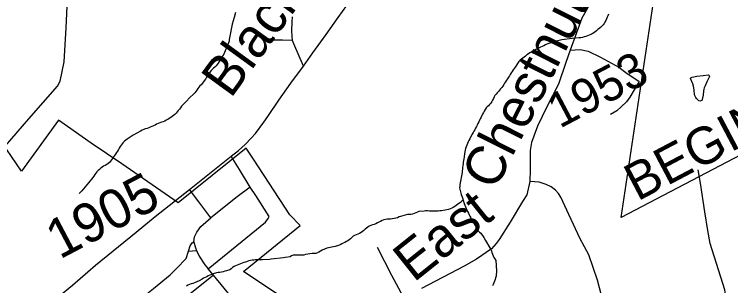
# Model space of a CAD drawing. Extents: x 1379448 to 1382868, y 593769 to 596827.
# Drawn here: x 1379666.4 to 1379935.9, y 595497.8 to 595600.1 of the extents above; entities that cross this region are included whole.
import ezdxf

# ---------------------------------------------------------------- set-up
doc = ezdxf.new("R2010")
doc.units = 0
for name, color, linetype in [('Old_Level_11', 7, 'Continuous'), ('Old_Level_32', 7, 'Continuous'), ('Old_Level_35', 7, 'Continuous'), ('Old_Level_48', 7, 'Continuous'), ('Old_Level_49', 7, 'Continuous'), ('Old_Level_62', 7, 'Continuous'), ('Old_Level_8', 7, 'Continuous')]:
    doc.layers.add(name, color=color, linetype=linetype)

msp = doc.modelspace()

# ---------------------------------------------------------------- linework, layer by layer
at = {"layer": 'Old_Level_11'}
for p, q in [((1379894.75, 595523.47), (1379909.86, 595624.29)), ((1380038.89, 595599.46), (1379894.75, 595523.47))]:
    msp.add_line(p, q, dxfattribs=at)
at = {"layer": 'Old_Level_32'}
for points in [[(1379640.12, 595529.74), (1379643.82, 595532.3), (1379648.19, 595535.83), (1379652.41, 595539.5), (1379660.54, 595547.76), (1379671.85, 595560.64), (1379682.66, 595573), (1379683.63, 595574.88), (1379685.11, 595582.2), (1379685.85, 595595.01), (1379686.98, 595619.75), (1379687.08, 595622.03), (1379687.13, 595624.42), (1379687.25, 595625.44), (1379687.39, 595628.93), (1379687.49, 595632.65), (1379687.77, 595638.22), (1379687.48, 595646), (1379686.94, 595658.47)], [(1379899.06, 595630.19), (1379889.58, 595617.21), (1379886.27, 595610.7), (1379883.76, 595605.7), (1379879.92, 595598.7), (1379877.96, 595593.17), (1379875.58, 595586.55)], [(1379683.35, 595493.98), (1379688.24, 595498.01), (1379696.92, 595505.49), (1379712.22, 595517.91), (1379719.4, 595523.93), (1379732.24, 595534.03), (1379737.9, 595538.56), (1379748.01, 595546.67), (1379750.73, 595548.72), (1379753.22, 595551.06), (1379755.55, 595553.38), (1379757.18, 595555.22), (1379760.31, 595559.39), (1379761.72, 595561.6), (1379765.93, 595567.69), (1379770.47, 595574.1), (1379775.16, 595580.59), (1379778.74, 595585.58), (1379783.72, 595592.51), (1379788.24, 595598.85), (1379791.48, 595603.37)], [(1379875.58, 595586.55), (1379879.35, 595586.8), (1379882.36, 595586.26), (1379886.91, 595583.9), (1379893.81, 595580.13), (1379896.43, 595578.18), (1379901.51, 595574.72)], [(1379875.58, 595586.55), (1379873.89, 595581.91), (1379871.1, 595573.72), (1379866.78, 595565.26), (1379863.25, 595557.99), (1379860.94, 595551.72), (1379860.52, 595548.81), (1379860.43, 595545.83), (1379860.45, 595541.65), (1379860.35, 595537.12)], [(1379923.57, 595461.53), (1379926.3, 595467.79), (1379932.44, 595483.19), (1379933.97, 595487.9), (1379934.26, 595489.83), (1379934.28, 595492.82), (1379933.76, 595496.17), (1379928.2, 595513.67), (1379927.29, 595518.6), (1379926.27, 595525.62), (1379924.52, 595536.46), (1379923.75, 595541.51)], [(1379860.35, 595537.12), (1379859.21, 595532.1), (1379857.66, 595529.56), (1379852.97, 595521.73), (1379848.78, 595515.26), (1379847.74, 595513.74), (1379845.88, 595511.74), (1379840.23, 595507.84), (1379835.65, 595505.19), (1379819.59, 595496.7)], [(1379923.57, 595461.53), (1379917.03, 595465.49), (1379898.01, 595477), (1379894.52, 595479.95), (1379892.42, 595482.24), (1379890.47, 595485.05), (1379888.73, 595488.79), (1379885.86, 595499.84), (1379882.5, 595509.41), (1379879.34, 595515.46), (1379874.98, 595524.63), (1379872.01, 595531.16), (1379871.14, 595532.59), (1379869.97, 595533.81), (1379868.42, 595535.06), (1379866.55, 595535.92), (1379863.91, 595536.76), (1379860.35, 595537.12)], [(1379812.86, 595493.5), (1379808.42, 595501.66), (1379803.01, 595512.18)]]:
    msp.add_lwpolyline(points, dxfattribs=at)
at = {"layer": 'Old_Level_35'}
for p, q in [((1379731.9, 595510.79), (1379734.96, 595511.01)), ((1379741.35, 595501.72), (1379739.38, 595504.2))]:
    msp.add_line(p, q, dxfattribs=at)
for points in [[(1379771, 595590.16), (1379770.78, 595593.72), (1379770.98, 595597.38), (1379771, 595599.12)], [(1379771, 595590.16), (1379767.23, 595590.35), (1379763.32, 595590.36)], [(1379775.16, 595580.59), (1379771.52, 595588.94), (1379771, 595590.16)], [(1379901.51, 595574.72), (1379899.63, 595571.66), (1379897.94, 595568.82), (1379896.74, 595567.04), (1379894.76, 595565.19), (1379893.06, 595563.72), (1379890.75, 595562.27)], [(1379755.1, 595534.98), (1379751.17, 595541.63), (1379748.01, 595546.67)], [(1379740.35, 595523.42), (1379735.79, 595529.45), (1379732.24, 595534.03)], [(1379739.38, 595504.2), (1379760.86, 595521.73), (1379761.93, 595523.12), (1379762.29, 595523.86), (1379757.26, 595531.79), (1379755.1, 595534.98)], [(1379755.1, 595534.98), (1379750.23, 595531.3), (1379740.35, 595523.42)], [(1379733.98, 595514.3), (1379734.23, 595516.18), (1379735.06, 595518.03), (1379736.58, 595520.1), (1379740.35, 595523.42)], [(1379731.9, 595510.79), (1379732.57, 595512.85), (1379733.36, 595513.97), (1379733.98, 595514.3)], [(1379733.98, 595514.3), (1379734.49, 595512.03), (1379734.96, 595511.01)], [(1379705.01, 595485.66), (1379718.78, 595496.77), (1379724.96, 595501.92), (1379727.36, 595504.29), (1379730.99, 595508), (1379731.9, 595510.79)], [(1379734.96, 595511.01), (1379735.89, 595508.97), (1379738.09, 595505.62), (1379739.38, 595504.2)], [(1379741.35, 595501.72), (1379734.34, 595496.06), (1379711.06, 595477.68)], [(1379753.75, 595487.17), (1379749.3, 595491.92), (1379741.35, 595501.72)]]:
    msp.add_lwpolyline(points, dxfattribs=at)
at = {"layer": 'Old_Level_48'}
msp.add_line((1379706.83, 595543.73), (1379695.33, 595551.52), dxfattribs=at)
for points in [[(1379695.33, 595551.52), (1379682.96, 595560.25), (1379669.13, 595540.96), (1379663.48, 595549.25)], [(1379937.54, 595313.11), (1379935.68, 595324.14), (1379926.32, 595374.29), (1379931.87, 595375.52), (1379929.49, 595387.82), (1379937.84, 595389.12), (1379931.29, 595425.64), (1379904.13, 595417.61), (1379896.01, 595407.11), (1379890.61, 595410.69), (1379752.56, 595503.09), (1379773.98, 595520.53), (1379770.04, 595524.52), (1379756.34, 595545.51), (1379753.67, 595549.68), (1379728.08, 595528.98), (1379706.83, 595543.73)]]:
    msp.add_lwpolyline(points, dxfattribs=at)
at = {"layer": 'Old_Level_49'}
msp.add_line((1379706.83, 595543.73), (1379695.33, 595551.52), dxfattribs=at)
for points in [[(1379695.33, 595551.52), (1379682.96, 595560.25), (1379669.13, 595540.96), (1379663.48, 595549.25)], [(1379937.54, 595313.11), (1379935.68, 595324.14), (1379926.32, 595374.29), (1379931.87, 595375.52), (1379929.49, 595387.82), (1379937.84, 595389.12), (1379931.29, 595425.64), (1379904.13, 595417.61), (1379896.01, 595407.11), (1379890.61, 595410.69), (1379752.56, 595503.09), (1379773.98, 595520.53), (1379770.04, 595524.52), (1379756.34, 595545.51), (1379753.67, 595549.68), (1379728.08, 595528.98), (1379706.83, 595543.73)]]:
    msp.add_lwpolyline(points, dxfattribs=at)
at = {"layer": 'Old_Level_62'}
for points in [[(1379749.55, 595600.74), (1379749.06, 595598.91), (1379748.39, 595596.37), (1379748.24, 595595.73), (1379748.1, 595595.09), (1379747.58, 595592.52), (1379747.27, 595590.61), (1379747.16, 595589.97), (1379746.97, 595589.35), (1379746.75, 595588.73), (1379746.51, 595588.12), (1379746.26, 595587.5), (1379746, 595586.9), (1379745.73, 595586.3), (1379745.45, 595585.71), (1379745.16, 595585.12), (1379744.86, 595584.53), (1379744.55, 595583.95), (1379744.22, 595583.38), (1379743.88, 595582.82), (1379743.52, 595582.27), (1379743.14, 595581.74), (1379742.73, 595581.22), (1379742.32, 595580.71), (1379741.88, 595580.22), (1379741.38, 595579.81), (1379740.89, 595579.37), (1379740.45, 595578.88), (1379740.04, 595578.37), (1379739.64, 595577.84), (1379739.28, 595577.3), (1379738.93, 595576.74), (1379738.6, 595576.17), (1379738.27, 595575.6), (1379736.7, 595573.57), (1379736.24, 595573.09), (1379735.8, 595572.61), (1379735.39, 595572.09), (1379735.04, 595571.53), (1379734.7, 595570.97), (1379734.32, 595570.45), (1379733.83, 595570.01), (1379732.37, 595568.68), (1379731.02, 595567.29), (1379730.13, 595566.36), (1379729.25, 595565.42), (1379728.85, 595564.9), (1379728.47, 595564.36), (1379728.09, 595563.82), (1379727.69, 595563.29), (1379727.28, 595562.79), (1379726.79, 595562.37), (1379725.76, 595561.57), (1379725.23, 595561.19), (1379724.69, 595560.8), (1379724.13, 595560.45), (1379723.57, 595560.13), (1379722.97, 595559.86), (1379722.36, 595559.62), (1379721.74, 595559.39), (1379721.12, 595559.16), (1379720.52, 595558.91), (1379719.92, 595558.64), (1379719.33, 595558.35), (1379718.74, 595558.07), (1379718.14, 595557.79), (1379717.55, 595557.52), (1379716.94, 595557.27), (1379716.31, 595557.08), (1379715.67, 595556.91), (1379715.06, 595556.69), (1379714.46, 595556.42), (1379713.88, 595556.1), (1379711.05, 595554.52), (1379708.87, 595553.09), (1379708.33, 595552.71), (1379707.82, 595552.29), (1379707.37, 595551.82), (1379706.98, 595551.29), (1379706.6, 595550.75), (1379706.24, 595550.21), (1379705.88, 595549.66), (1379705.52, 595549.1), (1379705.16, 595548.54), (1379704.81, 595547.98), (1379704.46, 595547.43), (1379704.1, 595546.87), (1379703.73, 595546.33), (1379703.36, 595545.79), (1379702.97, 595545.26), (1379702.58, 595544.74), (1379702.17, 595544.24), (1379701.7, 595543.8), (1379701.15, 595543.44)], [(1379889.94, 595600.19), (1379889.72, 595599.57), (1379889.47, 595598.96), (1379889.2, 595598.36), (1379888.92, 595597.76), (1379888.63, 595597.17), (1379888.3, 595596.6), (1379887.92, 595596.07), (1379887.49, 595595.59), (1379887, 595595.14), (1379886.5, 595594.72), (1379885.98, 595594.31), (1379885.45, 595593.91), (1379884.93, 595593.51), (1379884.39, 595593.13), (1379883.84, 595592.77), (1379883.26, 595592.47), (1379882.66, 595592.2), (1379882.05, 595591.97), (1379881.42, 595591.75), (1379880.79, 595591.55), (1379880.16, 595591.37), (1379879.52, 595591.22), (1379878.87, 595591.2), (1379877.57, 595591.08), (1379876.26, 595590.92), (1379872.4, 595590.42), (1379869.85, 595589.9), (1379866.8, 595588.78), (1379866.2, 595588.53)], [(1379866.2, 595588.53), (1379865.6, 595588.25), (1379865, 595587.97), (1379864.41, 595587.69), (1379863.83, 595587.4), (1379863.24, 595587.1), (1379862.65, 595586.8), (1379862.07, 595586.51), (1379861.49, 595586.2), (1379860.92, 595585.87), (1379860.36, 595585.52), (1379859.82, 595585.15), (1379859.29, 595584.76), (1379858.75, 595584.37), (1379858.23, 595583.97), (1379857.71, 595583.57), (1379857.19, 595583.16), (1379856.68, 595582.75), (1379856.18, 595582.35), (1379854.78, 595580.21), (1379854.42, 595579.66), (1379854.07, 595579.11), (1379853.71, 595578.56), (1379853.36, 595578), (1379853.01, 595577.45), (1379852.66, 595576.89), (1379852.3, 595576.34), (1379851.95, 595575.78), (1379851.6, 595575.23), (1379851.24, 595574.68), (1379850.88, 595574.13), (1379850.52, 595573.59), (1379850.15, 595573.04), (1379849.78, 595572.51), (1379849.38, 595571.98), (1379848.95, 595571.48), (1379848.51, 595571), (1379848.06, 595570.51), (1379847.63, 595570.02), (1379847.23, 595569.5), (1379846.91, 595568.93), (1379846.65, 595568.33), (1379846.37, 595567.73), (1379846.02, 595567.17), (1379845.63, 595566.65), (1379845.2, 595566.14), (1379844.77, 595565.64), (1379844.34, 595565.16), (1379843.88, 595564.78), (1379843.54, 595564.21), (1379843.22, 595563.64), (1379842.9, 595563.07), (1379842.59, 595562.48), (1379842.28, 595561.9), (1379841.99, 595561.32), (1379841.69, 595560.73), (1379841.4, 595560.14), (1379841.12, 595559.55), (1379840.84, 595558.95), (1379840.55, 595558.36), (1379840.26, 595557.77), (1379839.97, 595557.19), (1379839.66, 595556.6), (1379839.32, 595556.04), (1379838.98, 595555.48), (1379838.67, 595554.91), (1379838.05, 595553.74), (1379837.75, 595553.16), (1379837.45, 595552.57), (1379837.16, 595551.98), (1379836.88, 595551.39), (1379836.63, 595550.78), (1379836.4, 595550.17), (1379836.21, 595549.55), (1379836.05, 595548.91), (1379835.93, 595548.27), (1379835.81, 595547.62), (1379835.6, 595546.32), (1379835.49, 595545.67), (1379835.4, 595545.02), (1379835.3, 595544.37), (1379835.22, 595543.72), (1379835.13, 595543.07), (1379835.05, 595542.41), (1379834.97, 595541.77), (1379834.89, 595541.11), (1379834.86, 595540.46), (1379834.8, 595539.8), (1379834.69, 595539.16), (1379834.55, 595538.52), (1379834.41, 595537.88), (1379834.27, 595537.23), (1379834.16, 595536.58), (1379834.07, 595535.94), (1379833.99, 595535.28), (1379833.91, 595534.63), (1379834.58, 595532.11), (1379834.76, 595531.48), (1379834.97, 595530.86), (1379835.28, 595529.98)], [(1379921.41, 595576.38), (1379923.25, 595576.75), (1379925.53, 595577.09), (1379927.45, 595577.29), (1379927.72, 595577.2), (1379927.9, 595577.04), (1379927.98, 595576.8), (1379927.86, 595576.37), (1379927, 595574.62), (1379926.31, 595573.15), (1379925.95, 595572.37), (1379925.81, 595571.87), (1379925.73, 595571.22), (1379925.6, 595569.61), (1379925.25, 595567.94), (1379925.07, 595567.64), (1379924.72, 595567.45), (1379924.39, 595567.39), (1379924.01, 595567.54), (1379923.09, 595568.32), (1379922.8, 595568.7), (1379922.52, 595569.2), (1379922.34, 595569.79), (1379922.21, 595571.46), (1379922.13, 595572.32), (1379921.96, 595573.01), (1379921.64, 595573.85), (1379920.78, 595575.9), (1379920.76, 595576.07), (1379920.9, 595576.2), (1379921.15, 595576.3), (1379921.41, 595576.38)], [(1379701.15, 595543.44), (1379700.57, 595543.12), (1379699.99, 595542.8), (1379699.43, 595542.43), (1379698.9, 595542.04), (1379698.39, 595541.63), (1379697.9, 595541.18), (1379697.48, 595540.69), (1379697.06, 595540.18), (1379696.67, 595539.65), (1379696.28, 595539.13), (1379695.89, 595538.6), (1379694.28, 595536.52), (1379691.75, 595533.51), (1379690.82, 595532.57)], [(1379835.28, 595529.98), (1379834.75, 595529.6), (1379834.23, 595529.2), (1379833.7, 595528.81), (1379833.17, 595528.41), (1379832.64, 595528.03), (1379832.09, 595527.67), (1379831.54, 595527.33), (1379830.96, 595527.03), (1379830.35, 595526.77), (1379829.72, 595526.55), (1379829.1, 595526.36), (1379828.46, 595526.21), (1379827.81, 595526.1), (1379827.16, 595526.02), (1379826.5, 595525.96), (1379825.85, 595525.92), (1379825.19, 595525.89), (1379824.53, 595525.88), (1379823.88, 595525.87), (1379823.22, 595525.89), (1379822.57, 595525.92), (1379821.91, 595525.95), (1379821.26, 595525.96), (1379820.6, 595525.92), (1379818.65, 595525.8), (1379818.05, 595525.55), (1379817.45, 595525.27), (1379816.84, 595524.99), (1379816.24, 595524.77), (1379815.59, 595524.68), (1379814.93, 595524.67), (1379814.28, 595524.58), (1379811.75, 595523.89), (1379811.13, 595523.7), (1379810.55, 595523.38), (1379809.91, 595523.23), (1379809.26, 595523.1), (1379808.61, 595523), (1379807.96, 595522.92), (1379807.31, 595522.88), (1379806.65, 595522.83), (1379806, 595522.72), (1379805.36, 595522.56), (1379804.75, 595522.33), (1379804.16, 595522.05), (1379803.57, 595521.75), (1379803, 595521.44), (1379802.41, 595521.15), (1379801.8, 595520.89), (1379801.17, 595520.68), (1379800.55, 595520.47), (1379799.94, 595520.22), (1379799.39, 595519.9), (1379798.87, 595519.5), (1379798.37, 595519.06), (1379797.88, 595518.61), (1379797.37, 595518.19), (1379796.83, 595517.83), (1379796.25, 595517.53), (1379795.65, 595517.26), (1379795.04, 595516.99), (1379794.44, 595516.72), (1379793.87, 595516.41), (1379793.36, 595516), (1379792.92, 595515.5), (1379791.91, 595514.72), (1379791.33, 595514.41), (1379790.74, 595514.11), (1379790.15, 595513.82), (1379789.56, 595513.53), (1379788.97, 595513.25), (1379788.37, 595512.97), (1379787.16, 595512.53), (1379786.53, 595512.38), (1379785.88, 595512.29), (1379785.22, 595512.22), (1379784.58, 595512.11), (1379783.96, 595511.91), (1379782.16, 595511.16), (1379781.59, 595510.83), (1379781.02, 595510.47), (1379780.44, 595510.17), (1379779.82, 595509.99), (1379779.18, 595509.91), (1379778.51, 595509.87), (1379775.91, 595509.5), (1379775.27, 595509.36), (1379774.61, 595509.29), (1379773.96, 595509.28), (1379773.3, 595509.31), (1379772.64, 595509.34), (1379771.98, 595509.34), (1379771.34, 595509.28), (1379770.71, 595509.05), (1379770.18, 595508.72), (1379768.25, 595508.39), (1379767.61, 595508.29), (1379763.05, 595507.8), (1379762.4, 595507.72)], [(1379835.28, 595529.98), (1379835.7, 595528.74), (1379835.92, 595528.12), (1379836.17, 595527.51), (1379836.42, 595526.91), (1379836.69, 595526.31), (1379836.96, 595525.71), (1379837.25, 595525.12), (1379837.53, 595524.53), (1379837.82, 595523.94), (1379838.13, 595523.36), (1379838.43, 595522.78), (1379838.75, 595522.2), (1379839.08, 595521.64), (1379839.42, 595521.07), (1379840.31, 595519.62), (1379840.6, 595519.03), (1379840.98, 595518.5), (1379841.44, 595518.03), (1379841.89, 595517.55), (1379843.03, 595515.97), (1379843.74, 595514.89), (1379845.35, 595512.06), (1379845.66, 595511.47), (1379845.92, 595510.88), (1379846.03, 595510.25), (1379846.3, 595509.65), (1379846.57, 595509.05), (1379846.86, 595508.46), (1379847.15, 595507.86), (1379847.51, 595507.32), (1379847.59, 595506.68), (1379847.63, 595506.02), (1379847.69, 595505.36), (1379847.73, 595504.7), (1379847.76, 595504.04), (1379847.77, 595503.38), (1379847.76, 595502.73), (1379847.72, 595502.08), (1379847.63, 595501.44), (1379847.47, 595500.8), (1379847.28, 595500.17), (1379847.06, 595499.54), (1379846.6, 595498.3), (1379846.36, 595497.7)], [(1379762.4, 595507.72), (1379759.78, 595507.54), (1379759.13, 595507.51), (1379758.47, 595507.53), (1379757.82, 595507.55), (1379757.16, 595507.53), (1379756.51, 595507.46), (1379755.85, 595507.38), (1379755.2, 595507.26), (1379754.57, 595507.11), (1379753.94, 595506.92), (1379753.33, 595506.71), (1379752.7, 595506.48), (1379752.09, 595506.26), (1379751.47, 595506.02), (1379750.86, 595505.77), (1379750.26, 595505.51), (1379749.66, 595505.25), (1379749.06, 595504.97), (1379748.5, 595504.64), (1379747.99, 595504.21), (1379747.47, 595503.83), (1379746.24, 595503.39), (1379745.61, 595503.21), (1379744.97, 595503.05), (1379744.33, 595502.91), (1379743.69, 595502.78), (1379743.04, 595502.73), (1379742.4, 595502.64), (1379741.14, 595502.31), (1379740.55, 595502.04), (1379739.95, 595501.76), (1379739.35, 595501.47), (1379738.77, 595501.18), (1379738.18, 595500.89), (1379737.6, 595500.58), (1379737.04, 595500.25), (1379735.94, 595499.6), (1379734.15, 595498.84), (1379733.54, 595498.6), (1379732.9, 595498.45), (1379732.26, 595498.28), (1379731.69, 595497.98), (1379731.15, 595497.61)]]:
    msp.add_lwpolyline(points, dxfattribs=at)

# ---------------------------------------------------------------- texts
at = {"layer": 'Old_Level_11'}
for s, height, rotation, p in [('Black', 14.764, 53.9661, (1379747.78, 595568.04)), ('BEGIN PROJECT', 14, 27.7977, (1379900.85, 595529.45)), ('Chestnut', 14.764, 63.3136, (1379847.28, 595533.22)), ('East', 14.764, 38.618, (1379816.66, 595498.78))]:
    msp.add_text(s, height=height, rotation=rotation, dxfattribs=at).set_placement(p)
at = {"layer": 'Old_Level_8'}
for s, height, p in [('1953', 13.123, (1379871.57, 595556.89)), ('1905', 14.764, (1379683.42, 595507.56))]:
    msp.add_text(s, height=height, rotation=27.7977, dxfattribs=at).set_placement(p)

doc.saveas('drawing.dxf')
